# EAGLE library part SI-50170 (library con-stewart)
Ethernet Connector MagJack (R) Source: www.stewartconnector.com .. si-50170.pdf
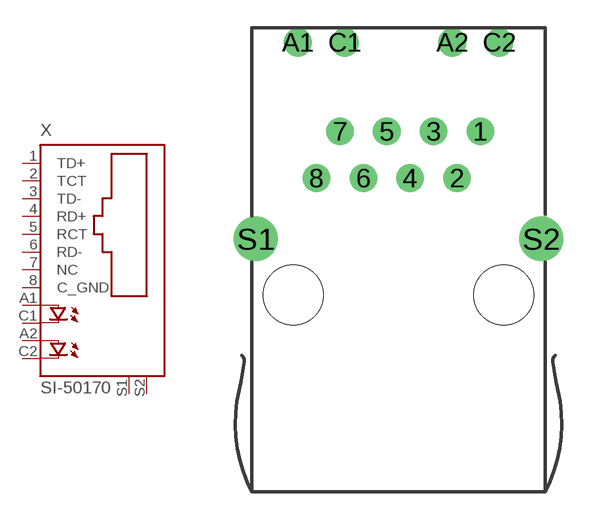
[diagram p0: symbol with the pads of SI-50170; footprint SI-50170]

Designator prefix X

## SI-50170 (OC_FARNELL: unknown; OC_NEWARK: unknown)  [SI-50170]
1  TD+  pas
2  TCT  pas
3  TD-  pas
4  RD+  pas
5  RCT  pas
6  RD-  pas
7  NC  pas
8  C_GND  pas
A1  A  pas
A2  A1  pas
C1  C  pas
C2  C1  pas
S1  S1  pas
S2  S2  pas

## Footprint SI-50170 (pad centres in mm)
Ethernet Connector (MagJack) Source: si-50170.pdf
drill 0.9 pad 1.5 round: 1 4.445,5.842; 2 3.175,3.302; 3 1.905,5.842; 4 0.635,3.302; 5 -0.635,5.842; 6 -1.905,3.302; 7 -3.175,5.842; 8 -4.445,3.302
drill 1.016 pad 1.5 round: A1 -5.461,10.668; A2 2.921,10.668; C1 -2.921,10.668; C2 5.461,10.668
drill 1.6 pad 2.2 round: S1 -7.747,0; S2 7.747,0
hole 3.251 at -5.715,-3.048
hole 3.251 at 5.715,-3.048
